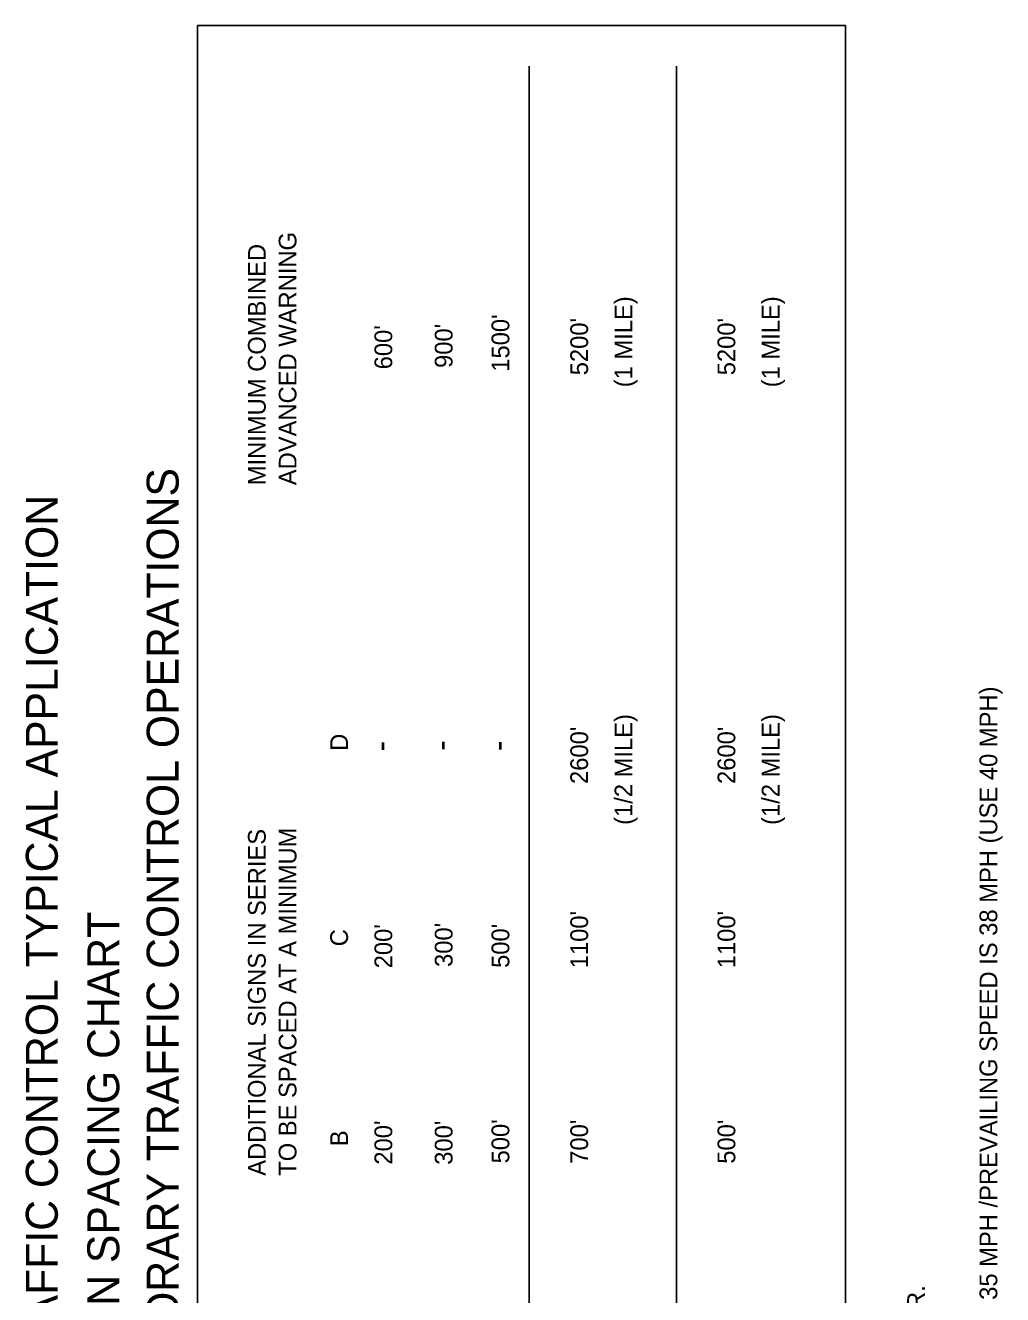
# Model space of a CAD drawing. Extents: x 610.92 to 617.75, y 610.91 to 620.34.
# Drawn here: x 610.921 to 614.226, y 616.047 to 620.337 of the extents above; entities that cross this region are included whole.
import ezdxf

# ---------------------------------------------------------------- set-up
doc = ezdxf.new("R2010")
doc.units = 0
doc.layers.add('DETL-NOTE', color=7, linetype='Continuous')
doc.layers.add('DETL-TITL', color=7, linetype='Continuous')

msp = doc.modelspace()

# ---------------------------------------------------------------- linework, layer by layer
at = {"layer": 'DETL-NOTE'}
for p, q in [((611.503, 620.3372), (611.503, 613.3204)), ((613.6939, 620.3372), (611.503, 620.3372)), ((613.6939, 613.3204), (613.6939, 620.3372)), ((612.6246, 620.1996), (612.6246, 613.3828)), ((613.1225, 620.1996), (613.1225, 613.3828))]:
    msp.add_line(p, q, dxfattribs=at)

# ---------------------------------------------------------------- texts
for s, height, p in [('ADVANCED WARNING', 0.06, (611.8374, 618.7828)), ('MINIMUM COMBINED', 0.06, (611.7334, 618.7828)), ('(1 MILE)', 0.06, (612.9733, 619.1138)), ('(1 MILE)', 0.06, (613.4712, 619.1138)), ("1500'", 0.06, (612.5573, 619.1664)), ("5200'", 0.06, (612.8237, 619.1544)), ("5200'", 0.06, (613.3216, 619.1544)), ("600'", 0.06, (612.1613, 619.1745)), ("900'", 0.06, (612.3653, 619.1792)), ('BELOW EXAMPLE TWO LANES, ONE-WAY ROADWAY /SPEED LIMIT IS 35 MPH /PREVAILING SPEED IS 38 MPH (USE 40 MPH)', 0.06, (614.2077, 613.314)), ('(1/2 MILE)', 0.06, (612.9733, 617.6346)), ('(1/2 MILE)', 0.06, (613.4712, 617.6346)), ('D', 0.06, (612.0117, 617.8848)), ("2600'", 0.06, (612.8237, 617.7728)), ("2600'", 0.06, (613.3216, 617.7728)), ('-', 0.08, (612.1613, 617.883)), ('-', 0.08, (612.3653, 617.8848)), ('-', 0.08, (612.5573, 617.8844)), ('ADDITIONAL SIGNS IN SERIES', 0.06, (611.7334, 616.4484)), ('TO BE SPACED AT A MINIMUM', 0.06, (611.8374, 616.4484)), ("1100'", 0.06, (612.8237, 617.1499)), ("1100'", 0.06, (613.3216, 617.1499)), ("200'", 0.06, (612.1613, 617.1497)), ("300'", 0.06, (612.3653, 617.1543)), ("500'", 0.06, (612.5573, 617.151)), ('C', 0.06, (612.0117, 617.2241)), ('B', 0.06, (612.0117, 616.5484)), ("200'", 0.06, (612.1613, 616.486)), ("300'", 0.06, (612.3653, 616.4856)), ("500'", 0.06, (612.5573, 616.4902)), ("700'", 0.06, (612.8237, 616.489)), ("500'", 0.06, (613.3216, 616.489)), ('SPEED LIMIT OR PREVAILING TRAVEL SPEED, WHICHEVER IS HIGHER.', 0.06, (613.9629, 613.314))]:
    msp.add_text(s, height=height, rotation=90, dxfattribs=at).set_placement(p)
at = {"layer": 'DETL-TITL'}
for s, p in [('STANDARD TEMPORARY TRAFFIC CONTROL OPERATIONS', (611.4389, 614.7084)), ('TEMPORARY TRAFFIC CONTROL TYPICAL APPLICATION', (611.0301, 614.802)), ('SIGN SPACING CHART', (611.2381, 615.7599))]:
    msp.add_text(s, height=0.108, rotation=90, dxfattribs=at).set_placement(p)

doc.saveas('drawing.dxf')
